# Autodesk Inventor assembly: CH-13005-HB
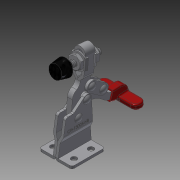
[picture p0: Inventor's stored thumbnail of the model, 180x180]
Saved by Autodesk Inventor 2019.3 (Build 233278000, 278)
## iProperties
Company: Î¢ÈíÖÐ¹ú
Created: 2012-09
Part Number: CH-13005-HB
Material: Ogólny
Description: STEP AP203
Document SubType Name: Assembly
Designer: CADENGINEERING4
Stock Number: DOCISK PIONOWY
Sending System: SolidWorks 2010
Preprocessor: SwSTEP 2.0
Title: CH-13005-HB.STEP
Author: Î¢ÈíÓÃ»§
Revision Number: ÈÎºÎ
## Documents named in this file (9)
- D:\Vault_2016\Projekty\Clamptek\STRONA\Vertical toggle clamp\CH-13005-HB\CH-13005-HB_OTWARTY.iam
- D:\Vault_2016\Projekty\Clamptek\STRONA\Vertical toggle clamp\CH-13005-HB\CH-FW-100.ipt
- D:\Vault_2016\Projekty\Clamptek\STRONA\Vertical toggle clamp\CH-13005-HB\CH-13005-04 CONNECTING-PLATE.ipt
- D:\Vault_2016\Projekty\Clamptek\STRONA\Vertical toggle clamp\CH-13005-HB\CH-13005-05 .ipt
- D:\Vault_2016\Projekty\Clamptek\STRONA\Vertical toggle clamp\CH-13005-HB\CH-13005-02 U-BAR.ipt
- D:\Vault_2016\Projekty\Clamptek\STRONA\Vertical toggle clamp\CH-13005-HB\CH-FC-10138 Nut.ipt
- D:\Vault_2016\Projekty\Clamptek\STRONA\Vertical toggle clamp\CH-13005-HB\CH-13005-HB-01 FLANGED BASE.ipt
- D:\Vault_2016\Projekty\Clamptek\STRONA\Vertical toggle clamp\CH-13005-HB\CH-FC-10138 SPINDLE SUPPLIED.ipt
- D:\Vault_2016\Projekty\Clamptek\STRONA\Vertical toggle clamp\CH-13005-HB\CH-13005-03 T-HANDLE.ipt
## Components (14 placed, 14 different names)
1. CH-FW-100_1 — Zestawiające:20, Zestawiające:22, Zestawiające:23, Zestawiające:24, Zestawiające:25, Zestawiające:28, Kątowe:1
2. CH-13005-04 CONNECTING-PLATE_2 — Zestawiające:5, Zestawiające:6, Zestawiające:10, Zestawiające:15, Zestawiające:16
3. CH-13005-05 _3 — Zestawiające:12, Zestawiające:18
4. CH-13005-02 U-BAR_4 — Zestawiające:2, Zestawiające:4, Zestawiające:5, Zestawiające:7, Zestawiające:9, Zestawiające:10, Zestawiające:20, Zestawiające:21, Zestawiające:23, Zestawiające:24, Kątowe:1, Kątowe:2, Zestawiające:30
5. CH-FC-10138 Nut_5 — Zestawiające:26, Zestawiające:27
6. CH-13005-HB-01 FLANGED BASE_6 — Zestawiające:1, Zestawiające:2, Zestawiające:7, Zestawiające:8, Zestawiające:11, Zestawiające:12, Zestawiające:17, Zestawiające:18
7. CH-FW-100_7 — Zestawiające:21, Zestawiające:22, Zestawiające:26, Zestawiające:27, Równoległe:1, Kątowe:2
8. CH-13005-05 _8 — Zestawiające:11, Zestawiające:17
9. CH-13005-05 _9 — Zestawiające:13, Zestawiające:16
10. CH-FC-10138 Nut_10 — Zestawiające:25, Zestawiające:28, Zestawiające:29
11. CH-13005-05 _11 — Zestawiające:14, Zestawiające:15
12. CH-FC-10138 SPINDLE SUPPLIED_12 — Zestawiające:29, Równoległe:1
13. CH-13005-03 T-HANDLE_13 — Zestawiające:1, Zestawiające:3, Zestawiające:6, Zestawiające:8, Zestawiające:30
14. CH-13005-04 CONNECTING-PLATE_14 — Zestawiające:3, Zestawiające:4, Zestawiające:9, Zestawiające:13, Zestawiające:14
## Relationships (32: Mate 29, Angle 2, Flush 1)
- Zestawiające:1 [Mate]: CH-13005-HB-01 FLANGED BASE_6 ↔ CH-13005-03 T-HANDLE_13
- Zestawiające:2 [Mate]: CH-13005-02 U-BAR_4 ↔ CH-13005-HB-01 FLANGED BASE_6
- Zestawiające:3 [Mate]: CH-13005-03 T-HANDLE_13 ↔ CH-13005-04 CONNECTING-PLATE_14
- Zestawiające:4 [Mate]: CH-13005-02 U-BAR_4 ↔ CH-13005-04 CONNECTING-PLATE_14
- Zestawiające:5 [Mate]: CH-13005-04 CONNECTING-PLATE_2 ↔ CH-13005-02 U-BAR_4
- Zestawiające:6 [Mate]: CH-13005-04 CONNECTING-PLATE_2 ↔ CH-13005-03 T-HANDLE_13
- Zestawiające:7 [Mate]: CH-13005-02 U-BAR_4 ↔ CH-13005-HB-01 FLANGED BASE_6
- Zestawiające:8 [Mate]: CH-13005-HB-01 FLANGED BASE_6 ↔ CH-13005-03 T-HANDLE_13
- Zestawiające:9 [Mate]: CH-13005-02 U-BAR_4 ↔ CH-13005-04 CONNECTING-PLATE_14
- Zestawiające:10 [Mate]: CH-13005-04 CONNECTING-PLATE_2 ↔ CH-13005-02 U-BAR_4
- Zestawiające:11 [Mate]: CH-13005-HB-01 FLANGED BASE_6 ↔ CH-13005-05 _8
- Zestawiające:12 [Mate]: CH-13005-05 _3 ↔ CH-13005-HB-01 FLANGED BASE_6
- Zestawiające:13 [Mate]: CH-13005-05 _9 ↔ CH-13005-04 CONNECTING-PLATE_14
- Zestawiające:14 [Mate]: CH-13005-05 _11 ↔ CH-13005-04 CONNECTING-PLATE_14
- Zestawiające:15 [Mate]: CH-13005-04 CONNECTING-PLATE_2 ↔ CH-13005-05 _11
- Zestawiające:16 [Mate]: CH-13005-04 CONNECTING-PLATE_2 ↔ CH-13005-05 _9
- Zestawiające:17 [Mate]: CH-13005-HB-01 FLANGED BASE_6 ↔ CH-13005-05 _8
- Zestawiające:18 [Mate]: CH-13005-05 _3 ↔ CH-13005-HB-01 FLANGED BASE_6
- Zestawiające:20 [Mate]: CH-FW-100_1 ↔ CH-13005-02 U-BAR_4
- Zestawiające:21 [Mate]: CH-13005-02 U-BAR_4 ↔ CH-FW-100_7
- Zestawiające:22 [Mate]: CH-FW-100_1 ↔ CH-FW-100_7
- Zestawiające:23 [Mate]: CH-FW-100_1 ↔ CH-13005-02 U-BAR_4
- Zestawiające:24 [Mate]: CH-FW-100_1 ↔ CH-13005-02 U-BAR_4
- Zestawiające:25 [Mate]: CH-FW-100_1 ↔ CH-FC-10138 Nut_10
- Zestawiające:26 [Mate]: CH-FC-10138 Nut_5 ↔ CH-FW-100_7
- Zestawiające:27 [Mate]: CH-FC-10138 Nut_5 ↔ CH-FW-100_7
- Zestawiające:28 [Mate]: CH-FW-100_1 ↔ CH-FC-10138 Nut_10
- Zestawiające:29 [Mate]: CH-FC-10138 Nut_10 ↔ CH-FC-10138 SPINDLE SUPPLIED_12
- Równoległe:1 [Flush]: CH-FW-100_7 ↔ CH-FC-10138 SPINDLE SUPPLIED_12
- Kątowe:1 [Angle]: CH-FW-100_1 ↔ CH-13005-02 U-BAR_4
- Kątowe:2 [Angle]: CH-13005-02 U-BAR_4 ↔ CH-FW-100_7
- Zestawiające:30 [Mate]: CH-13005-02 U-BAR_4 ↔ CH-13005-03 T-HANDLE_13
